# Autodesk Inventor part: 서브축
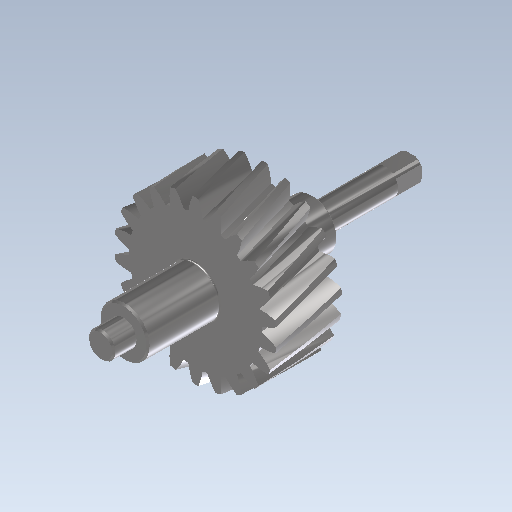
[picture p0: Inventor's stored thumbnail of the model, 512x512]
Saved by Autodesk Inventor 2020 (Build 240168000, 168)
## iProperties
CustomPartVersion: 1
Created: 2017-11
Part Number: 서브축
Material: 강철, 탄소
Document SubType Name: Modeling
Designer: mduedu
Categories: <?xml version="1.0" encoding="UTF-16"?> <MemberInstance><Categories><FamilyTemplate><FamilyTemplateParameter ValueType="xs:double" Id="1" ObjectReferenceKey="da
Density: 7.87 g/cm^3
Appearance: 반광택
Mass: 321.256 g
Surface Area: 116.557 cm^2
Volume: 40.8204 cm^3
Author: mduedu
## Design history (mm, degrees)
sketch "Sketch1"
  geometry: C1 r 24.776 at (0, 0)
  constraints: 1 centre point
  dimensions: "d0" = 49.55215 diameter of C1 (= da_da)
extrude "Extrusion1" new body sketch "Sketch1" distance "d1" = -20 (= da_b); taper "d2" = 0 deg
workplane "Work Plane2"
sketch "Sketch2"
  geometry: C1 r 24.776 at (0, 0) reference; C2 r 22.776 at (0, 0)
  constraints: 1 centre point, 1 coincident
  dimensions: "d3" = 45.55215 diameter of C2 (= da_dw)
feature "피치 지름" sketch "Sketch2" dims "d4" = 10, "d5" = 0
workplane "Work Plane8"
workplane "Work Plane9"
feature "스퍼 기어" dims "da_b" = -20, "da_d" = 45.55215, "da_aw" = 54.86964, "da_da" = 49.55215, "da_df" = 40.55215, "da_dw" = 45.55215, angle "da_beta" = 15 deg, "da_lefttooth" = 10, "da_righttooth" = 0
sketch "스케치3"
  geometry: C1 r 7.5 at (0, 0); 1 further point
  constraints: 1 centre point, 1 coincident
  dimensions: "d49" = 15 diameter of C1
extrude "돌출2" join sketch "스케치3" distance "d50" = 22; taper "d51" = 0 deg
sketch "스케치4"
  geometry: C1 r 4 at (0, 0); 1 further point
  constraints: 1 centre point, 1 coincident
  dimensions: "d52" = 8 diameter of C1
extrude "돌출3" join sketch "스케치4" distance "d53" = 7; taper "d54" = 0 deg
sketch "스케치5"
  geometry: C1 r 7.5 at (0, 0); 1 further point
  constraints: 1 centre point, 1 coincident
  dimensions: "d55" = 15 diameter of C1
extrude "돌출4" join sketch "스케치5" distance "d56" = 16; taper "d57" = 0 deg
sketch "스케치6"
  geometry: C1 r 4 at (0, 0); 1 further point
  constraints: 1 centre point, 1 coincident
  dimensions: "d58" = 8 diameter of C1
extrude "돌출5" join sketch "스케치6" distance "d59" = 30; taper "d60" = 0 deg
chamfer "모따기1" distance "d61" = 0.5; stored, may be unused: second distance "d62" = 2, angle "d63" = 45 deg
fillet "모깎기1" dims "d64" = 0.5
sketch "스케치7"
  geometry: L1 (-3.25, -3.25)-(3.25, -3.25); L2 (3.25, -3.25)-(3.25, 3.25); L3 (3.25, 3.25)-(-3.25, 3.25); L4 (-3.25, 3.25)-(-3.25, -3.25); L5 (-3.25, -3.25)-(3.25, 3.25); L6 (3.25, -3.25)-(-3.25, 3.25); L7 (-5, -5)-(5, -5); L8 (5, -5)-(5, 5); L9 (5, 5)-(-5, 5); L10 (-5, 5)-(-5, -5); L11 (-5, -5)-(5, 5); L12 (5, -5)-(-5, 5); 1 further point
  constraints: 24 end point, 4 midpoint, 4 parallel, 2 horizontal, 2 perpendicular
  dimensions: "d65" = 6.5 distance of L3.end L2.end; "d66" = 6.5 distance of L2.end L1.end; "d67" = 10 distance of L9.end L8.end; "d68" = 10 distance of L8.end L7.end
extrude "돌출6" cut sketch "스케치7" distance "d69" = 8; taper "d70" = 0 deg
body "Solid1"
body "Srf1"
other parameters: "d16" = 54.86964 (= da_aw), "d17" = 0, "d34" = 1.428 (computed from da_z), "d39" = 0, "d41" = 0, "d43" = 54.86964 (= da_aw), "d46" = 54.86964 (= da_aw), "d47" = 0, "d48" = 0
